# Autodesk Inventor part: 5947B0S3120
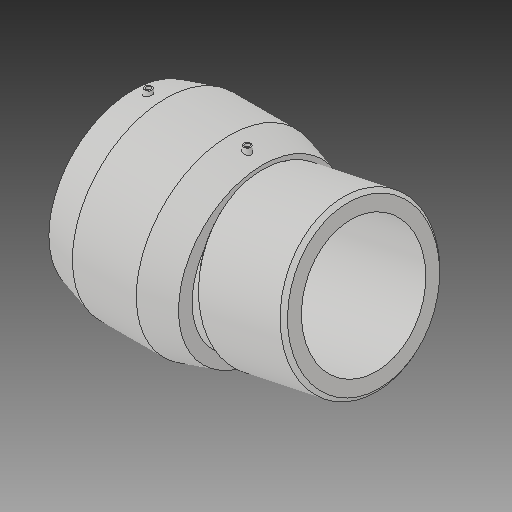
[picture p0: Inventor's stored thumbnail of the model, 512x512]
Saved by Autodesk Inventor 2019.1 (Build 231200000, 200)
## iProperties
Created: 2017-06
Part Number: 5947B0S3120
Material: Generic
Description: PLASSON ADJUSTABLE ELBOW (ONE SIDE) ASTM 12'' IPS
Document SubType Name: Modeling
Designer: KIM
Mass: 10909.3 g
Surface Area: 8060.11 cm^2
Volume: 10909.3 cm^3
Density: 1 g/cm^3
Appearance: Default
Author: KIM
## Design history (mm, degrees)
derived "5947BOS.ipt"
feature "Solid1::5947BOS.ipt"
tag "TaggingFeature1"
body "Solid1"
other parameters: "d0" = 268.0335, "d2" = 386.08, "d3" = 135.89, "d4" = 67.945, "d5" = 347.472, "d7" = 323.4, "d8" = 168 deg, "d10" = 54.356, "d11" = 18.11867, "d29" = 193.04, "d30" = 15, "d31" = 102.108, "d34" = 5 deg, "d41" = 4, "d42" = 14, "d43" = 0, "d48" = 291.06, "d55" = 79.2861, "d57" = 168 deg, "d62" = 3, "d63" = 0, "d65" = 510.54, "d66" = 323.4, "d67" = 291.06, "d68" = 135 deg, "d69" = 180.086, "d71" = 7.7216, "d74" = 145.53, "d_" = 323.4, "L_" = 510.54, "L_1" = 135.89, "D_" = 386.08, "A_" = 193.04, "L_0" = 148, "D_1" = 323.4, "L_2" = 180.086, "d54" = 132.1435
